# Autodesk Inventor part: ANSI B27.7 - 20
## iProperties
Component Type: 1
Library Location: C:\Program Files\Autodesk\Inventor 6\content
Library: local
SubLibrary: ANSI
Family: 1256
Member: 130
Member Major Revision: 1
Member Minor Revision: 1
Comments: To add or edit properties for Autodesk Inventor files, use iProperties.
Created: 2003-05
Part Number: ANSI B27.7 - 20
Vendor: Autodesk Inc.
Document SubType Name: Modeling
Designer: robert
Description: Anneau intérieur - type 3BM1
Standard: ANSI B27.7 20
Density: 1 g/cm^3
Alert: To add or edit properties for Autodesk Inventor files, use iProperties.
Control State: 0
Master: False
Checked Out: False
Shininess: 64.0
Length Units: 11269
Angle Units: 11279
Time Units: 11290
Mass Units: 11283
Length Display Precision: 3
Angle Display Precision: 2
Compacted: True
Density: 0.0
Volumn: 0.0
Area: 0.0
PropertySet Name: Model Information
Author: robert
Revision Number: 1
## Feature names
1. Corps [Extrusion]
